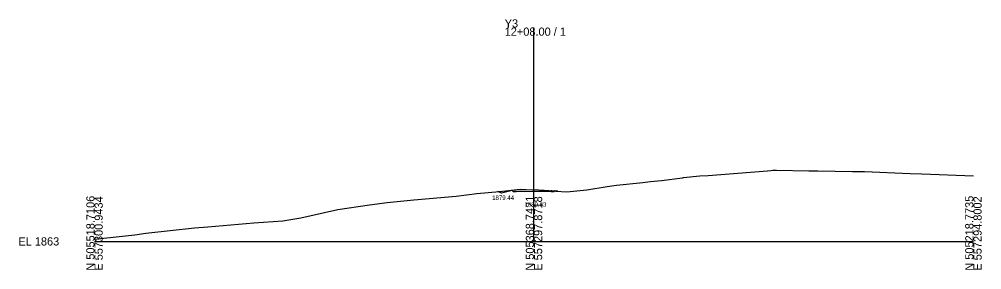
# Model space of a CAD drawing. Extents: x -26 to 1503, y -10 to 2064.
# Drawn here: x 1174.3 to 1502.8, y -9.7 to 75.9 of the extents above; entities that cross this region are included whole.
import ezdxf

# ---------------------------------------------------------------- set-up
doc = ezdxf.new("R2010")
doc.units = 0
for name, color, linetype in [('Exist Cross Section Cell', 7, 'Continuous'), ('Exist XS Ground Line', 7, 'Continuous'), ('Prop CMT Shld Paved Course 1', 7, 'Continuous'), ('Prop XS Ditch Standard Text', 7, 'Continuous'), ('Prop XS Earthwork Shape', 7, 'Continuous')]:
    doc.layers.add(name, color=color, linetype=linetype)

msp = doc.modelspace()

# ---------------------------------------------------------------- linework, layer by layer
at = {"layer": 'Exist Cross Section Cell'}
for p, q in [((1350, 0), (1350, 73.09)), ((1200, 0), (1350, 0)), ((1350, 0), (1500, 0))]:
    msp.add_line(p, q, dxfattribs=at)
at = {"layer": 'Exist XS Ground Line'}
msp.add_lwpolyline([(1200, 0.82), (1213.72, 2.29), (1217.56, 2.79), (1234.07, 4.62), (1238.62, 4.99), (1254.41, 6.37), (1264.22, 7.07), (1270.37, 8.1), (1283.07, 10.85), (1293.85, 12.52), (1299.85, 13.29), (1309.02, 14.26), (1323.45, 15.41), (1330.55, 16.34), (1338.23, 17.1), (1345.28, 17.88), (1349.47, 17.67), (1350, 17.63), (1361.2, 16.94), (1367.99, 17.62), (1374.97, 18.81), (1378.19, 19.23), (1387.16, 20.14), (1389.83, 20.44), (1393.53, 20.86), (1400.7, 21.77), (1401.04, 21.82), (1406.65, 22.37), (1409.43, 22.54), (1429.69, 24.15), (1430.84, 24.24), (1431.54, 24.3), (1432.75, 24.36), (1443.85, 24.17), (1446.86, 24.13), (1458.77, 23.91), (1462.82, 23.89), (1478.46, 23.2), (1482.41, 23.1), (1500, 22.42)], dxfattribs=at)
at = {"layer": 'Prop CMT Shld Paved Course 1'}
msp.add_lwpolyline([(1356.14, 17.28), (1355.88, 17.28)], dxfattribs=at)
at = {"layer": 'Prop XS Earthwork Shape'}
for points in [[(1338.89, 16.45), (1337.69, 17.05), (1338.23, 17.1), (1345.28, 17.88), (1349.47, 17.67), (1350, 17.65), (1343.88, 17.53), (1342.89, 17.45), (1342.54, 17.36)], [(1350, 17.65), (1343.88, 17.53), (1342.89, 17.45), (1342.54, 17.36), (1342.89, 17.02), (1343.88, 17.03), (1350, 17.15), (1355.88, 17.03), (1356.88, 17.02), (1357.06, 17.2)], [(1357.22, 17.37), (1358.14, 17.14), (1357.06, 17.2)]]:
    msp.add_lwpolyline(points, close=True, dxfattribs=at)

# ---------------------------------------------------------------- texts
at = {"layer": 'Exist Cross Section Cell'}
for s, p in [('Y3', (1340, 73.09)), ('12+08.00 / 1', (1340, 70.29)), ('EL 1863', (1174, -1.4))]:
    msp.add_text(s, height=2.8, dxfattribs=at).set_placement(p)
for s, p in [('N 505518.7106', (1200, -10)), ('E 557300.9434', (1202.8, -10)), ('N 505368.7421', (1350, -10)), ('E 557297.8718', (1352.8, -10)), ('N 505218.7735', (1500, -10)), ('E 557294.8002', (1502.8, -10))]:
    msp.add_text(s, height=2.8, rotation=90, dxfattribs=at).set_placement(p)
at = {"layer": 'Prop XS Ditch Standard Text'}
for s, p in [('1879.44', (1335.72, 14.2)), ('1880.63', (1346.74, 11.86))]:
    msp.add_text(s, height=1.5, dxfattribs=at).set_placement(p)

doc.saveas('drawing.dxf')
